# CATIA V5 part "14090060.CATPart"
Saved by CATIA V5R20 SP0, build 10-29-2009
Part number: 14090060
Definition: NONE
Nomenclature: 14090060
Source: Unknown
Description: 14090060
Bounding box of the stored display mesh (mm): x -30 to 120, y -59 to 49.1, z -49.1 to 49.1
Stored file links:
  C:\Users\Utente\Desktop\IO LAVORO\3D X SITO CF\X SITO\PLASTICA\RF2\14090060.CATPart
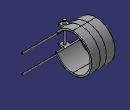
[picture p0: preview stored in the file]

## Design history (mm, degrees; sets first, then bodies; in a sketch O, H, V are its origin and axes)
Body1 "14090060" (main body)
  Solid1: solid without history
